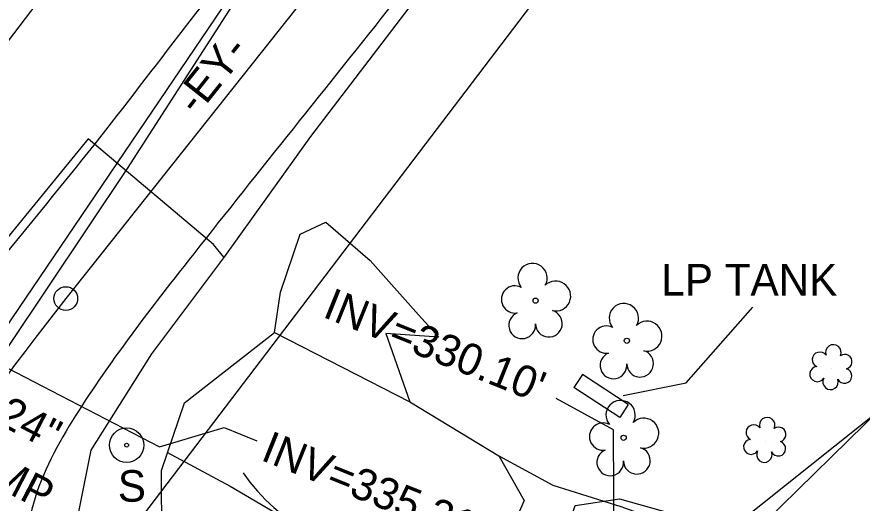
# Model space of a CAD drawing. Extents: x 2089016 to 2094354, y 862840 to 864725.
# Drawn here: x 2091346.4 to 2091453.5, y 863746.7 to 863808.3 of the extents above; entities that cross this region are included whole.
import ezdxf

# ---------------------------------------------------------------- set-up
doc = ezdxf.new("R2010")
doc.units = 0
for name, color, linetype in [('Exist Horizontal Alignment', 7, 'Continuous'), ('Exist Horizontal Alignment Station Label', 7, 'Continuous'), ('Exist Hydro Jurisdictional Stream or Body of Water', 7, 'Continuous'), ('Exist Hydro Stream Flow Arrow CELL', 7, 'Continuous'), ('Exist Other Culture AG Tank', 7, 'Continuous'), ('Exist Other Culture AG Tank Leader', 7, 'Continuous'), ('Exist Other Culture AG Tank Text', 7, 'Continuous'), ('Exist Other Culture Area Outline', 7, 'Continuous'), ('Exist Other Culture Sign Text', 7, 'Continuous'), ('Exist Property Line', 7, 'Continuous'), ('Exist Right of Way Line', 7, 'Continuous'), ('Exist Roads EOP', 7, 'Continuous'), ('Exist Structure Minor Pipes CMP 24 Inch', 7, 'Continuous'), ('Exist Structure Minor Pipes CMP 24 Inch Leader', 7, 'Continuous'), ('Exist Structure Minor Pipes CMP 24 Inch Text', 7, 'Continuous'), ('Exist Structure Minor Pipes HDPE 36 Inch', 7, 'Continuous'), ('Exist Structure Minor Pipes HDPE 36 Inch Invert', 7, 'Continuous'), ('Exist Structure Minor Pipes HDPE 36 Inch Leader', 7, 'Continuous'), ('Exist Utilities Gas UG Line SUE LOS B', 7, 'Continuous'), ('Exist Utilities Sanitary Sewer UG Line', 7, 'Continuous'), ('Exist Utilities Water UG Line SUE LOS C', 7, 'Continuous'), ('Exist Vegetation Hedge Row', 7, 'Continuous'), ('Exist Vegetation Shrub CELL', 7, 'Continuous'), ('Exist Vegetation Tree CELL', 7, 'Continuous'), ('Exist Vegetation Woods Line', 7, 'Continuous'), ('Prop Conc Driveway', 7, 'Continuous')]:
    doc.layers.add(name, color=color, linetype=linetype)

msp = doc.modelspace()

# ---------------------------------------------------------------- linework, layer by layer
at = {"layer": 'Exist Horizontal Alignment'}
msp.add_line((2091395.86644594, 863827.1675470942), (2091352.6134513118, 863772.6429277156), dxfattribs=at)
msp.add_arc((2091607.228981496, 863570.6628995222), 325, 141.57592603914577, 153.58273838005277, dxfattribs=at)
at = {"layer": 'Exist Horizontal Alignment Station Label'}
msp.add_circle((2091352.6134513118, 863772.6429277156), 1.5, dxfattribs=at)
at = {"layer": 'Exist Hydro Jurisdictional Stream or Body of Water'}
msp.add_lwpolyline([(2091365.4267000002, 863753.1838), (2091373.4542, 863748.8453), (2091383.1367, 863743.1598000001), (2091398.8094, 863734.3958), (2091409.0506, 863725.8441), (2091409.5491, 863721.353)], dxfattribs=at)
at = {"layer": 'Exist Hydro Stream Flow Arrow CELL'}
msp.add_lwpolyline([(2091375.0751329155, 863750.5462061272), (2091375.9246832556, 863749.3515637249), (2091376.9193106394, 863748.231185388), (2091377.915817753, 863747.1386946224), (2091378.975618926, 863746.1539946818), (2091380.1165128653, 863745.2086516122), (2091381.3169414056, 863744.3153242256), (2091382.5401176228, 863743.5101092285)], dxfattribs=at)
at = {"layer": 'Exist Other Culture AG Tank'}
for points in [[(2091423.88603367, 863759.2350490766), (2091418.07553367, 863763.0360490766), (2091416.9806663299, 863761.3623509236)], [(2091423.88603367, 863759.2350490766), (2091422.79116633, 863757.5613509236), (2091416.9806663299, 863761.3623509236)]]:
    msp.add_lwpolyline(points, dxfattribs=at)
at = {"layer": 'Exist Other Culture AG Tank Leader'}
msp.add_lwpolyline([(2091423.2461901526, 863760.3413666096), (2091431.215698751, 863761.9600115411), (2091439.6472078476, 863771.5562636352)], dxfattribs=at)
at = {"layer": 'Exist Other Culture Area Outline'}
msp.add_lwpolyline([(2091432.441782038, 863712.31156035), (2091426.8357351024, 863719.6635224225), (2091424.8893797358, 863724.0703385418), (2091426.0011031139, 863728.4920100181), (2091424.8170505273, 863731.678633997), (2091422.1717969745, 863733.2148118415), (2091418.3095100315, 863732.0315582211), (2091415.0409726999, 863733.8943755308), (2091415.0000531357, 863740.0775910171), (2091417.1391861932, 863746.394284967), (2091422.76146799, 863747.2754663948), (2091431.6479845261, 863744.752490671), (2091438.265070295, 863742.0121652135), (2091442.3756741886, 863736.8848809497), (2091443.8444120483, 863732.0363395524), (2091444.2735709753, 863726.2109780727), (2091443.8454782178, 863722.6687169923), (2091441.0094385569, 863717.5521270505), (2091436.5411990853, 863713.1277543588), (2091433.848728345, 863711.6885355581), (2091432.441782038, 863712.31156035)], dxfattribs=at)
at = {"layer": 'Exist Property Line'}
msp.add_line((2091407.1543656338, 863710.9601327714), (2091503.717, 863805.6478), dxfattribs=at)
at = {"layer": 'Exist Right of Way Line'}
for p, q in [((2091373.7601676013, 863842.767762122), (2091307.393561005, 863755.4565226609)), ((2091413.5660667, 863812.5106902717), (2091352.6280128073, 863732.3412000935))]:
    msp.add_line(p, q, dxfattribs=at)
at = {"layer": 'Exist Roads EOP'}
for points in [[(2090159.8571, 864177.4522), (2090180.6725, 864168.7302000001), (2090222.8594, 864151.6485), (2090264.3934, 864134.6019), (2090306.0047000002, 864117.7894), (2090347.2409, 864101.0471000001), (2090392.9939, 864082.5727), (2090433.2011, 864065.09), (2090472.8293000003, 864048.9636), (2090514.7308, 864032.4301), (2090559.9738, 864014.0483000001), (2090601.369, 863997.1904), (2090646.2914000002, 863978.8154), (2090688.9540000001, 863961.2748000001), (2090733.3817, 863942.9564), (2090770.0545, 863927.3349), (2090814.5164, 863908.7231), (2090858.9124, 863890.9963), (2090901.1465, 863874.1742), (2090939.8657000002, 863858.2796), (2090962.7205, 863848.636), (2090997.5425, 863834.7175), (2091036.0659, 863819.0768), (2091075.6024, 863802.4824), (2091112.8771, 863787.7685), (2091153.6392, 863770.6456), (2091194.6668, 863753.4881), (2091234.0738, 863737.2293), (2091276.5693000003, 863719.3300000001), (2091296.5569, 863710.7485), (2091332.881, 863695.6705), (2091370.7143000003, 863680.0496), (2091411.4527, 863662.8458), (2091427.0088, 863655.9048000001), (2091440.1865, 863646.8024000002), (2091448.8258, 863640.6190000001), (2091463.6724, 863633.8477), (2091467.987, 863632.1682), (2091469.1099, 863631.0712000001), (2091469.9741, 863630.0355), (2091470.3678, 863629.277)], [(2091458.6303000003, 863915.3002), (2091455.432, 863907.1622), (2091438.1719, 863872.8925000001), (2091417.8171, 863841.3111), (2091394.128, 863810.135), (2091368.8269000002, 863778.3267), (2091355.5953, 863760.4843), (2091347.9526, 863737.9204), (2091353.0504, 863717.6041), (2091353.0352, 863717.5561), (2091357.066, 863712.8221), (2091361.5023, 863708.9890000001), (2091398.612, 863693.5742), (2091435.1692, 863678.9551), (2091472.8795, 863664.1351), (2091513.0668, 863651.4162), (2091550.2818, 863640.4362000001), (2091559.5856, 863639.1286), (2091561.1682000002, 863638.354), (2091573.0702000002, 863633.8493), (2091588.6146, 863630.0184), (2091610.9193, 863627.5724), (2091621.3267, 863629.0367)], [(2091316.7113000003, 863747.7583), (2091320.1289, 863750.3175), (2091334.1135, 863765.1209), (2091358.4026, 863794.9062), (2091381.8452, 863824.2414), (2091385.2841000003, 863828.9459000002), (2091386.1673000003, 863832.0459), (2091386.6408, 863833.9939), (2091391.0508000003, 863839.8685), (2091394.8528, 863844.4761000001), (2091397.513, 863845.7681), (2091399.3615, 863846.6572), (2091401.0266, 863848.6498000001), (2091412.8683, 863867.486), (2091431.9472, 863899.973)]]:
    msp.add_spline(points, degree=3, dxfattribs=at)
at = {"layer": 'Exist Structure Minor Pipes CMP 24 Inch'}
msp.add_line((2091329.0122, 863772.2348), (2091364.5038, 863753.8619), dxfattribs=at)
at = {"layer": 'Exist Structure Minor Pipes CMP 24 Inch Leader'}
msp.add_lwpolyline([(2091364.5037999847, 863753.8619000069), (2091372.6712074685, 863756.3193526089), (2091376.8292119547, 863754.6016069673)], dxfattribs=at)
at = {"layer": 'Exist Structure Minor Pipes HDPE 36 Inch'}
msp.add_lwpolyline([(2091422.1142999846, 863731.7260999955), (2091576.9103426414, 863855.1811126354), (2091581.4254530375, 863856.5031449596), (2091588.4146239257, 863859.0712077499), (2091593.3257440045, 863861.3372631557), (2091597.9798577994, 863863.313311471), (2091603.293987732, 863866.3783864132), (2091607.4530894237, 863870.3144826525), (2091614.0492507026, 863875.5496106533), (2091619.4933838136, 863880.1697236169), (2091630.2476467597, 863889.6919564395), (2091672.7946, 863927.5499999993)], dxfattribs=at)
at = {"layer": 'Exist Structure Minor Pipes HDPE 36 Inch Leader'}
msp.add_lwpolyline([(2091422.1142999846, 863731.7260999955), (2091422.0177175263, 863756.0046513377), (2091414.7577096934, 863759.9686797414)], dxfattribs=at)
at = {"layer": 'Exist Utilities Gas UG Line SUE LOS B'}
for points in [[(2091490.4776, 863668.0603), (2091475.9759, 863673.4851), (2091454.7935000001, 863681.9523), (2091442.977, 863687.3758), (2091425.4537000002, 863692.4735), (2091405.1451, 863699.4609), (2091382.1647, 863707.9082), (2091366.1108, 863716.317), (2091358.0052, 863723.3572), (2091353.0253000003, 863739.4785), (2091355.8224, 863753.4128), (2091363.5069, 863765.6465), (2091372.7623, 863777.9747), (2091383.6628, 863793.1623), (2091402.9612, 863818.4864000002), (2091414.6806, 863834.229), (2091432.9613000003, 863863.0215), (2091438.2912, 863868.6516000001), (2091446.7832000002, 863880.5545)], [(2091372.6572, 863777.8975), (2091371.3338, 863779.4914), (2091355.4273000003, 863792.8696000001), (2091344.5694, 863779.5206), (2091330.4521, 863762.4258), (2091320.4004, 863753.7452000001), (2091310.932, 863750.2977000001)]]:
    msp.add_lwpolyline(points, dxfattribs=at)
at = {"layer": 'Exist Utilities Sanitary Sewer UG Line'}
msp.add_lwpolyline([(2091692.1334745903, 864500.8281898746), (2091501.0105, 864105.5082999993), (2091469.7102999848, 863953.2015999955), (2091320.5947000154, 863732.9499999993), (2090957.2668000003, 863880.9680999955), (2090681.314099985, 863994.8830999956), (2090015.2597000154, 864266.0974999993)], dxfattribs=at)
at = {"layer": 'Exist Utilities Water UG Line SUE LOS C'}
msp.add_lwpolyline([(2091311.6855445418, 863687.8033647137), (2091328.3286351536, 863730.0968295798), (2091345.3731179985, 863766.5845376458), (2091360.4500303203, 863789.1048067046), (2091425.8551233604, 863890.7840576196), (2091445.8704824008, 863937.4077015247), (2091455.2710898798, 863961.801153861)], dxfattribs=at)
at = {"layer": 'Exist Vegetation Hedge Row'}
for points in [[(2091379.049648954, 863768.3215136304), (2091379.83632711, 863773.4638791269), (2091382.2921230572, 863780.8132914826), (2091385.564852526, 863782.3295141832), (2091391.1610908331, 863777.4704702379), (2091397.3138939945, 863770.5770707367), (2091399.8669927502, 863767.7629120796), (2091393.1788985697, 863768.215609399), (2091396.221268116, 863759.5341126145)], [(2091407.460308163, 863752.7038558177), (2091414.3382970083, 863748.9973080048), (2091422.955080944, 863746.2790752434), (2091426.5852490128, 863744.9578123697), (2091419.9261826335, 863741.7620312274), (2091415.8097524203, 863735.4857081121), (2091417.331253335, 863730.4748343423), (2091424.4088061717, 863726.6435506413), (2091429.724087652, 863720.7924211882), (2091432.6962298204, 863715.6769064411), (2091434.1789514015, 863710.1783970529)]]:
    msp.add_lwpolyline(points, dxfattribs=at)
at = {"layer": 'Exist Vegetation Shrub CELL'}
for p, q in [((2091449.6338328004, 863763.764310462), (2091449.6338328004, 863763.764310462)), ((2091441.246489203, 863754.5494965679), (2091441.246489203, 863754.5494965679))]:
    msp.add_line(p, q, dxfattribs=at)
for centre, radius, start, end in [((2091449.8626829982, 863765.8047500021), 0.9900450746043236, 334.8390694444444, 200.47173888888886), ((2091448.1510866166, 863764.8911013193), 0.9678345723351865, 35.89076388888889, 245.42164722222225), ((2091451.305852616, 863764.6332280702), 0.9287983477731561, 284.45671944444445, 126.08612222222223), ((2091447.8335721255, 863763.0599201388), 0.9548337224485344, 95.10992222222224, 327.95341111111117), ((2091451.2708885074, 863762.8353082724), 0.9373148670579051, 204.99133055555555, 73.46011666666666), ((2091449.5054822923, 863762.0806318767), 0.9835814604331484, 151.2796583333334, 21.387019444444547), ((2091441.4753394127, 863756.5899361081), 0.9900450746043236, 334.8390694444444, 200.47173888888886), ((2091439.763743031, 863755.6762874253), 0.9678345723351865, 35.89076388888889, 245.42164722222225), ((2091442.9185090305, 863755.4184141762), 0.9287983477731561, 284.45671944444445, 126.08612222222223), ((2091439.4462285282, 863753.8451062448), 0.9548337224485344, 95.10992222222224, 327.95341111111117), ((2091442.88354491, 863753.6204943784), 0.9373148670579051, 204.99133055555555, 73.46011666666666), ((2091441.118138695, 863752.8658179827), 0.9835814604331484, 151.2796583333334, 21.387019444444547)]:
    msp.add_arc(centre, radius, start, end, dxfattribs=at)
at = {"layer": 'Exist Vegetation Tree CELL'}
for p, q in [((2091412.1369499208, 863772.3725190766), (2091412.1369499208, 863772.3725190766)), ((2091423.7057286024, 863767.2881644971), (2091423.7057286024, 863767.2881644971)), ((2091423.293541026, 863754.9937535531), (2091423.293541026, 863754.9937535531))]:
    msp.add_line(p, q, dxfattribs=at)
for centre in [(2091412.1369499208, 863772.3725190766), (2091423.7057285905, 863767.2881644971), (2091423.2935410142, 863754.9937535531)]:
    msp.add_circle(centre, 0.32596012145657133, dxfattribs=at)
for centre, radius, start, end in [((2091411.7520666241, 863775.2458115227), 1.855853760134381, 330.165075, 219.7133527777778), ((2091409.5315627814, 863772.5262193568), 1.7266185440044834, 62.66361111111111, 279.3457), ((2091414.6858670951, 863772.9611019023), 1.89900326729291, 257.1011, 134.1999305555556), ((2091413.8098153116, 863769.4730202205), 1.6982906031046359, 181.28216388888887, 74.55999166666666), ((2091423.320845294, 863770.1614569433), 1.855853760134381, 330.165075, 219.7133527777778), ((2091410.4328418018, 863769.2516889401), 1.6890867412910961, 111.56708055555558, 6.231044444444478), ((2091421.1003414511, 863767.4418647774), 1.7266185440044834, 62.66361111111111, 279.3457), ((2091426.2546457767, 863767.8767473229), 1.89900326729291, 257.1011, 134.1999305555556), ((2091422.0016204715, 863764.1673343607), 1.6890867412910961, 111.56708055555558, 6.231044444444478), ((2091425.3785939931, 863764.3886656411), 1.6982906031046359, 181.28216388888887, 74.55999166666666), ((2091422.9086577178, 863757.8670459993), 1.855853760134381, 330.165075, 219.7133527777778), ((2091425.8424582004, 863755.5823363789), 1.89900326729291, 257.1011, 134.1999305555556), ((2091420.6881538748, 863755.1474538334), 1.7266185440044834, 62.66361111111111, 279.3457), ((2091421.5894328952, 863751.8729234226), 1.6890867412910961, 111.56708055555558, 6.231044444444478), ((2091424.9664064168, 863752.094254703), 1.6982906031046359, 181.28216388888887, 74.55999166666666)]:
    msp.add_arc(centre, radius, start, end, dxfattribs=at)
at = {"layer": 'Exist Vegetation Woods Line'}
msp.add_lwpolyline([(2091379.049648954, 863768.3215136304), (2091396.221268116, 863759.5341126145), (2091407.460308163, 863752.7038558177), (2091410.6706628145, 863747.0473375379), (2091407.030575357, 863738.6820078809), (2091397.0941486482, 863733.1547056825), (2091383.492919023, 863730.3072912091), (2091372.9619852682, 863735.1835118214), (2091364.7622691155, 863742.1506207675), (2091364.7408980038, 863750.8318709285), (2091367.6469490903, 863759.414749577), (2091379.049648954, 863768.3215136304)], dxfattribs=at)
at = {"layer": 'Prop Conc Driveway'}
for radius in [2.1799154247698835, 0.24011715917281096]:
    msp.add_circle((2091360.3185, 863754.0591999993), radius, dxfattribs=at)

# ---------------------------------------------------------------- texts
at = {"layer": 'Exist Horizontal Alignment'}
msp.add_text('-EY-', height=3.999999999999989, rotation=51.57592603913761, dxfattribs=at).set_placement((2091369.2524962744, 863795.7039108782))
at = {"layer": 'Exist Other Culture AG Tank Text'}
msp.add_text('LP TANK', height=4, dxfattribs=at).set_placement((2091428.0672718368, 863773.0247884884))
at = {"layer": 'Exist Other Culture Sign Text'}
msp.add_text('S', height=4, dxfattribs=at).set_placement((2091359.204632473, 863746.8923056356))
at = {"layer": 'Exist Structure Minor Pipes CMP 24 Inch Text'}
for s, p in [('24"', (2091343.7011941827, 863756.8683586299)), ('CMP', (2091339.1884618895, 863751.0969238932))]:
    msp.add_text(s, height=4, rotation=332.63079949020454, dxfattribs=at).set_placement(p)
at = {"layer": 'Exist Structure Minor Pipes HDPE 36 Inch Invert'}
for s, height, p in [("INV=330.10'", 4, (2091385.012539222, 863770.3602046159)), ("INV=335.21'", 4.000000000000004, (2091377.1686866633, 863752.2298124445))]:
    msp.add_text(s, height=height, rotation=338.1164486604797, dxfattribs=at).set_placement(p)

doc.saveas('drawing.dxf')
